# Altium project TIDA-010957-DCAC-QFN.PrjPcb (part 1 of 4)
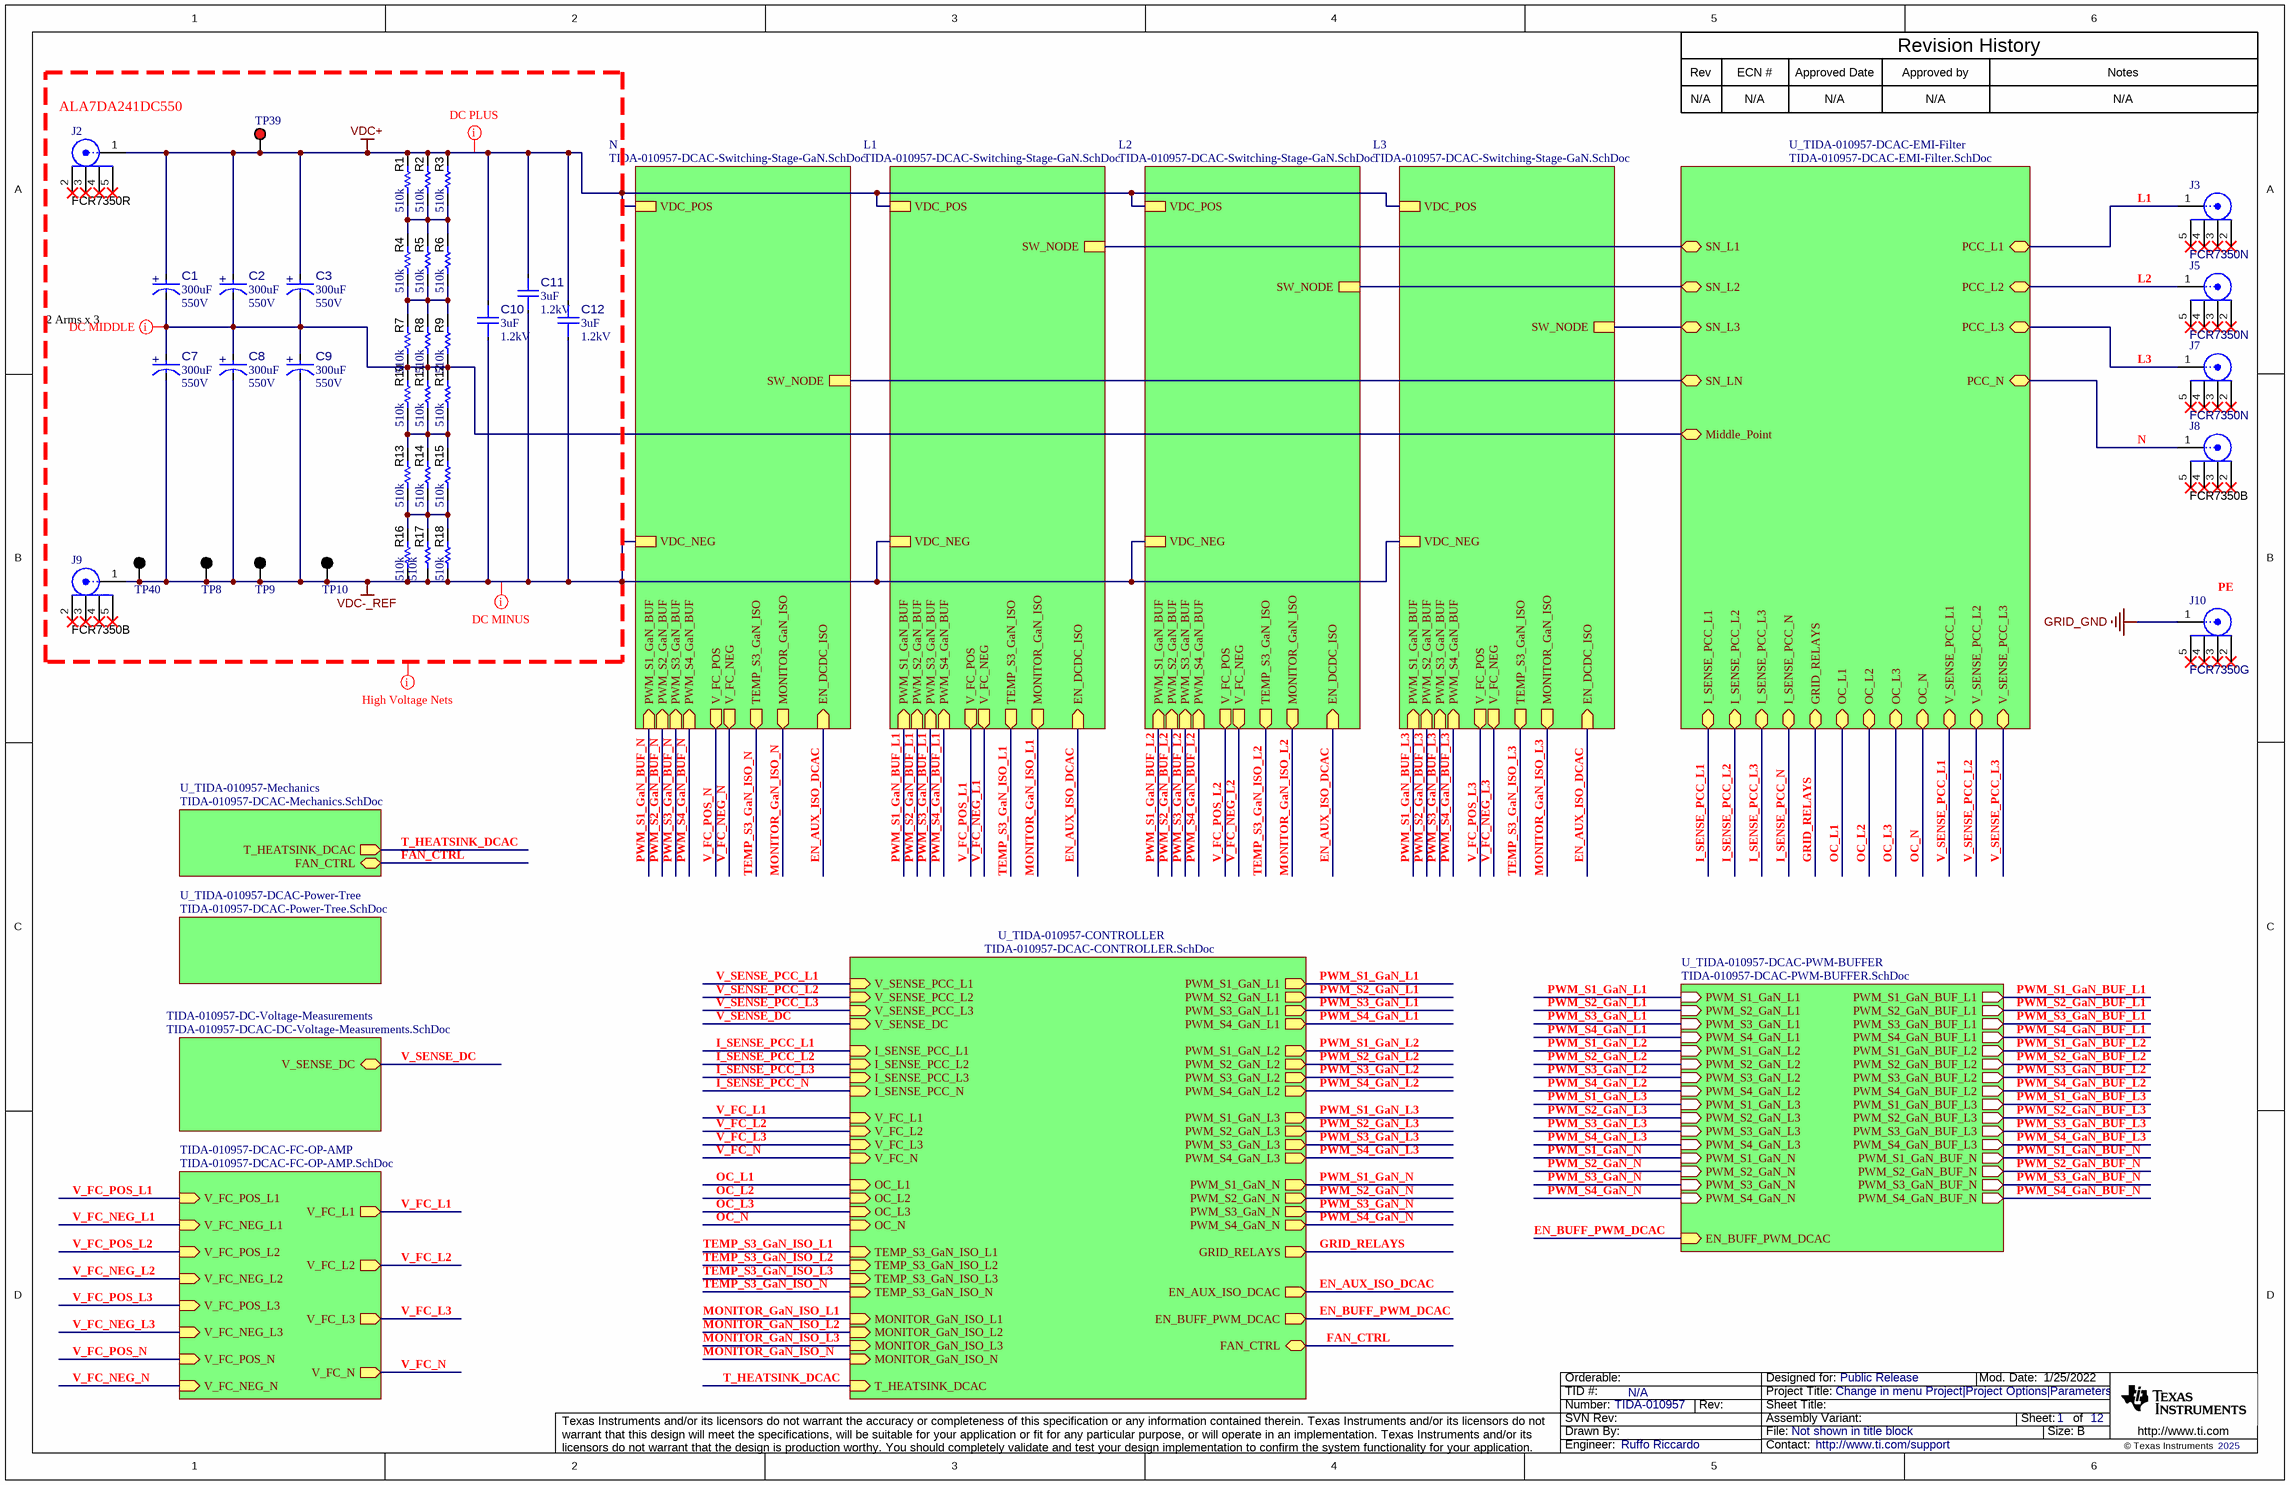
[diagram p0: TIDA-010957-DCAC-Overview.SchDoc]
CopyrightYear: 2025; PCB_Layout: Ruffo Riccardo; PCB_Rev: E1; PRJ_Customer: Public Release; PRJ_Engineer: Ruffo Riccardo; PRJ_Number: TIDA-010957; PRJ_Title: Change in menu Project|Project Options|Parameters; TechSupport: http://www.ti.com/support; TID: N/A
12 sheets, 1287 parts. Net scope: hierarchical (ports join the sheet entries above them; power ports are global).
Board file: TIDA-010957-DCAC-QFN-E1.PcbDoc
Sheets:
  TIDA-010957-DCAC-Overview.SchDoc
    U_TIDA-010957-CONTROLLER = TIDA-010957-DCAC-CONTROLLER.SchDoc
      U_TIDA-010957-DCAC-CAN = TIDA-010957-DCAC-CAN.SchDoc
    N = TIDA-010957-DCAC-Switching-Stage-GaN.SchDoc
    U_TIDA-010957-DCAC-EMI-Filter = TIDA-010957-DCAC-EMI-Filter.SchDoc
      TIDA-010957-DCAC-Current-Sensing = TIDA-010957-DCAC-Current-Sensing.SchDoc
      TIDA-010957-DCAC-Measurements-Voltages-AC = TIDA-010957-DCAC-Measurements-Voltages-AC.SchDoc
    TIDA-010957-DC-Voltage-Measurements = TIDA-010957-DCAC-DC-Voltage-Measurements.SchDoc
    TIDA-010957-DCAC-FC-OP-AMP = TIDA-010957-DCAC-FC-OP-AMP.SchDoc
    U_TIDA-010957-DCAC-PWM-BUFFER = TIDA-010957-DCAC-PWM-BUFFER.SchDoc
    U_TIDA-010957-DCAC-Power-Tree = TIDA-010957-DCAC-Power-Tree.SchDoc
    U_TIDA-010957-Mechanics = TIDA-010957-DCAC-Mechanics.SchDoc
    L1 = TIDA-010957-DCAC-Switching-Stage-GaN.SchDoc
    L2 = TIDA-010957-DCAC-Switching-Stage-GaN.SchDoc
    L3 = TIDA-010957-DCAC-Switching-Stage-GaN.SchDoc

## Sheet TIDA-010957-DCAC-Overview.SchDoc
size 431 x 279 mm; Date: Not shown in title block; ApprovedBy: Not shown in title block; CheckedBy: Not shown in title block; Author: Not shown in title block; CompanyName: Not shown in title block; Engineer: Not shown in title block; Organization: Not shown in title block; Address1: Not shown in title block; Address2: Not shown in title block; Address3: Not shown in title block; Address4: Not shown in title block; DocumentNumber: 1; Revision: Use project parameter SCH_Rev; SheetNumber: 1; SheetTotal: 12; PageSetup: Record=PageOptions¦CenterHorizontal=True¦CenterVertical=True¦PrintScale=1.00¦XCorrection=1.00¦YCorrection=1.00¦PrintKind=0¦BorderSize=5000000¦LeftOffset=0¦BottomOffset=0¦Orientation=2¦PaperLength=1000¦PaperWidth=1000¦Scale=100¦PaperSource=15¦PrintQuality=600¦MediaType=1¦DitherType=10¦PaperKind=Letter¦PrintScaleMode=1

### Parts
C1  ValueDisplayed: 300uF  VDC_V: 550V  [FP-ALA7DA301CF550_RADIAL-MFG]  (hidden comment: ALA7DA301CF550)
C2  ValueDisplayed: 300uF  VDC_V: 550V  [FP-ALA7DA301CF550_RADIAL-MFG]  (hidden comment: ALA7DA301CF550)
C3  ValueDisplayed: 300uF  VDC_V: 550V  [FP-ALA7DA301CF550_RADIAL-MFG]  (hidden comment: ALA7DA301CF550)
C7  ValueDisplayed: 300uF  VDC_V: 550V  [FP-ALA7DA301CF550_RADIAL-MFG]  (hidden comment: ALA7DA301CF550)
C8  ValueDisplayed: 300uF  VDC_V: 550V  [FP-ALA7DA301CF550_RADIAL-MFG]  (hidden comment: ALA7DA301CF550)
C9  ValueDisplayed: 300uF  VDC_V: 550V  [FP-ALA7DA301CF550_RADIAL-MFG]  (hidden comment: ALA7DA301CF550)
C10  ValueDisplayed: 3uF  VDC_V: 1.2kV  [FP-B32774X1305K000_RADIAL-MFG]  (hidden comment: B32774X1305K000)
C11  ValueDisplayed: 3uF  VDC_V: 1.2kV  [FP-B32774X1305K000_RADIAL-MFG]  (hidden comment: B32774X1305K000)
C12  ValueDisplayed: 3uF  VDC_V: 1.2kV  [FP-B32774X1305K000_RADIAL-MFG]  (hidden comment: B32774X1305K000)
J2  FCR7350R  [Cliff_FCR7350R]
J3  FCR7350N  [FP-FCR7350N_CONN_BANANA_JACK-MFG]
J5  FCR7350N  [FP-FCR7350N_CONN_BANANA_JACK-MFG]
J7  FCR7350N  [FP-FCR7350N_CONN_BANANA_JACK-MFG]
J8  FCR7350B  [Cliff_FCR7350B]
J9  FCR7350B  [Cliff_FCR7350B]
J10  FCR7350G  [FP-FCR7350G_CONN_BANANA_JACK-MFG]
R1  ValueDisplayed: 510k  [1206]  (hidden comment: CRCW1206510KJNEA)
R2  ValueDisplayed: 510k  [1206]  (hidden comment: CRCW1206510KJNEA)
R3  ValueDisplayed: 510k  [1206]  (hidden comment: CRCW1206510KJNEA)
R4  ValueDisplayed: 510k  [1206]  (hidden comment: CRCW1206510KJNEA)
R5  ValueDisplayed: 510k  [1206]  (hidden comment: CRCW1206510KJNEA)
R6  ValueDisplayed: 510k  [1206]  (hidden comment: CRCW1206510KJNEA)
R7  ValueDisplayed: 510k  [1206]  (hidden comment: CRCW1206510KJNEA)
R8  ValueDisplayed: 510k  [1206]  (hidden comment: CRCW1206510KJNEA)
R9  ValueDisplayed: 510k  [1206]  (hidden comment: CRCW1206510KJNEA)
R10  ValueDisplayed: 510k  [1206]  (hidden comment: CRCW1206510KJNEA)
R11  ValueDisplayed: 510k  [1206]  (hidden comment: CRCW1206510KJNEA)
R12  ValueDisplayed: 510k  [1206]  (hidden comment: CRCW1206510KJNEA)
R13  ValueDisplayed: 510k  [1206]  (hidden comment: CRCW1206510KJNEA)
R14  ValueDisplayed: 510k  [1206]  (hidden comment: CRCW1206510KJNEA)
R15  ValueDisplayed: 510k  [1206]  (hidden comment: CRCW1206510KJNEA)
R16  ValueDisplayed: 510k  [1206]  (hidden comment: CRCW1206510KJNEA)
R17  ValueDisplayed: 510k  [1206]  (hidden comment: CRCW1206510KJNEA)
R18  ValueDisplayed: 510k  [1206]  (hidden comment: CRCW1206510KJNEA)
TP8  5011  [Keystone5011]  (value not drawn)
TP9  5011  [Keystone5011]  (value not drawn)
TP10  5011  [Keystone5011]  (value not drawn)
TP39  5010  [Keystone5010]  (value not drawn)
TP40  5011  [Keystone5011]  (value not drawn)

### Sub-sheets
L1 = TIDA-010957-DCAC-Switching-Stage-GaN.SchDoc: PWM_S2_GaN_BUF (in), EN_DCDC_ISO (in), PWM_S1_GaN_BUF (in), PWM_S3_GaN_BUF (in), VDC_POS, SW_NODE, PWM_S4_GaN_BUF (in), VDC_NEG, V_FC_POS (out), V_FC_NEG (out), TEMP_S3_GaN_ISO (out), MONITOR_GaN_ISO (out)
L2 = TIDA-010957-DCAC-Switching-Stage-GaN.SchDoc: PWM_S2_GaN_BUF (in), EN_DCDC_ISO (in), PWM_S1_GaN_BUF (in), PWM_S3_GaN_BUF (in), VDC_POS, SW_NODE, PWM_S4_GaN_BUF (in), VDC_NEG, V_FC_POS (out), V_FC_NEG (out), TEMP_S3_GaN_ISO (out), MONITOR_GaN_ISO (out)
L3 = TIDA-010957-DCAC-Switching-Stage-GaN.SchDoc: PWM_S2_GaN_BUF (in), EN_DCDC_ISO (in), PWM_S1_GaN_BUF (in), PWM_S3_GaN_BUF (in), VDC_POS, SW_NODE, PWM_S4_GaN_BUF (in), VDC_NEG, V_FC_POS (out), V_FC_NEG (out), TEMP_S3_GaN_ISO (out), MONITOR_GaN_ISO (out)
N = TIDA-010957-DCAC-Switching-Stage-GaN.SchDoc: PWM_S2_GaN_BUF (in), EN_DCDC_ISO (in), PWM_S1_GaN_BUF (in), PWM_S3_GaN_BUF (in), VDC_POS, SW_NODE, PWM_S4_GaN_BUF (in), VDC_NEG, V_FC_POS (out), V_FC_NEG (out), TEMP_S3_GaN_ISO (out), MONITOR_GaN_ISO (out)
TIDA-010957-DC-Voltage-Measurements = TIDA-010957-DCAC-DC-Voltage-Measurements.SchDoc: V_SENSE_DC (bidir)
TIDA-010957-DCAC-FC-OP-AMP = TIDA-010957-DCAC-FC-OP-AMP.SchDoc: V_FC_POS_L1 (in), V_FC_L1 (out), V_FC_POS_L2 (in), V_FC_POS_L3 (in), V_FC_POS_N (in), V_FC_NEG_L1 (in), V_FC_NEG_L2 (in), V_FC_NEG_L3 (in), V_FC_NEG_N (in), V_FC_L2 (out), V_FC_L3 (out), V_FC_N (out)
U_TIDA-010957-CONTROLLER = TIDA-010957-DCAC-CONTROLLER.SchDoc: PWM_S1_GaN_L1 (out), PWM_S2_GaN_L1 (out), PWM_S3_GaN_L1 (out), PWM_S4_GaN_L1 (out), PWM_S1_GaN_L2 (out), PWM_S2_GaN_L2 (out), PWM_S3_GaN_L2 (out), PWM_S4_GaN_L2 (out), PWM_S1_GaN_L3 (out), PWM_S2_GaN_L3 (out), PWM_S3_GaN_L3 (out), PWM_S4_GaN_L3 (out), PWM_S1_GaN_N (out), PWM_S2_GaN_N (out), PWM_S3_GaN_N (out), PWM_S4_GaN_N (out), V_SENSE_DC (in), I_SENSE_PCC_L1 (in), I_SENSE_PCC_L2 (in), I_SENSE_PCC_L3 (in), OC_L1 (in), OC_L2 (in), OC_L3 (in), V_SENSE_PCC_L1 (in), V_SENSE_PCC_L2 (in), V_SENSE_PCC_L3 (in), V_FC_L1 (in), V_FC_L2 (in), V_FC_L3 (in), V_FC_N (in), GRID_RELAYS (out), EN_BUFF_PWM_DCAC (out), EN_AUX_ISO_DCAC (out), TEMP_S3_GaN_ISO_L1 (in), MONITOR_GaN_ISO_L1 (in), TEMP_S3_GaN_ISO_L2 (in), TEMP_S3_GaN_ISO_L3 (in), TEMP_S3_GaN_ISO_N (in), MONITOR_GaN_ISO_L2 (in), MONITOR_GaN_ISO_L3 (in), MONITOR_GaN_ISO_N (in), OC_N (in), I_SENSE_PCC_N (in), FAN_CTRL (bidir), T_HEATSINK_DCAC (in)
U_TIDA-010957-DCAC-EMI-Filter = TIDA-010957-DCAC-EMI-Filter.SchDoc: SN_L1 (bidir), SN_L2 (bidir), SN_L3 (bidir), SN_LN (bidir), PCC_L1 (bidir), PCC_L2 (bidir), PCC_L3 (bidir), PCC_N (bidir), OC_L1 (bidir), OC_L2 (bidir), OC_L3 (bidir), V_SENSE_PCC_L1 (bidir), V_SENSE_PCC_L2 (bidir), V_SENSE_PCC_L3 (bidir), I_SENSE_PCC_L1 (bidir), I_SENSE_PCC_L2 (bidir), I_SENSE_PCC_L3 (bidir), GRID_RELAYS (bidir), Middle_Point (bidir), I_SENSE_PCC_N (bidir), OC_N (bidir)
U_TIDA-010957-DCAC-Power-Tree = TIDA-010957-DCAC-Power-Tree.SchDoc: no entries
U_TIDA-010957-DCAC-PWM-BUFFER = TIDA-010957-DCAC-PWM-BUFFER.SchDoc: PWM_S1_GaN_BUF_L1 (out), PWM_S2_GaN_BUF_L1 (out), PWM_S3_GaN_BUF_L1 (out), PWM_S4_GaN_BUF_L1 (out), PWM_S1_GaN_BUF_L2 (out), PWM_S2_GaN_BUF_L2 (out), PWM_S3_GaN_BUF_L2 (out), PWM_S4_GaN_BUF_L2 (out), PWM_S1_GaN_BUF_L3 (out), PWM_S2_GaN_BUF_L3 (out), PWM_S3_GaN_BUF_L3 (out), PWM_S4_GaN_BUF_L3 (out), PWM_S1_GaN_BUF_N (out), PWM_S2_GaN_BUF_N (out), PWM_S3_GaN_BUF_N (out), PWM_S4_GaN_BUF_N (out), PWM_S1_GaN_L1 (in), PWM_S2_GaN_L1 (in), PWM_S3_GaN_L1 (in), PWM_S4_GaN_L1 (in), PWM_S1_GaN_L2 (in), PWM_S2_GaN_L2 (in), PWM_S3_GaN_L2 (in), PWM_S4_GaN_L2 (in), PWM_S1_GaN_L3 (in), PWM_S2_GaN_L3 (in), PWM_S3_GaN_L3 (in), PWM_S4_GaN_L3 (in), PWM_S1_GaN_N (in), PWM_S2_GaN_N (in), PWM_S3_GaN_N (in), PWM_S4_GaN_N (in), EN_BUFF_PWM_DCAC (in)
U_TIDA-010957-Mechanics = TIDA-010957-DCAC-Mechanics.SchDoc: T_HEATSINK_DCAC (out), FAN_CTRL (bidir)

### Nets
GRID_GND: J10.1
VDC+: C1.2(ANODE) C2.2(ANODE) C3.2(ANODE) C10.2 C11.2 C12.2 J2.1 R1.2 R2.2 R3.2 TP39.1 ; sheet N/VDC_POS, sheet L1/VDC_POS, sheet L2/VDC_POS, sheet L3/VDC_POS
VDC-_REF: C7.1(CATHODE) C8.1(CATHODE) C9.1(CATHODE) C10.1 C11.1 C12.1 J9.1 R16.1 R17.1 R18.1 TP8.1 TP9.1 TP10.1 TP40.1 ; sheet N/VDC_NEG, sheet L1/VDC_NEG, sheet L2/VDC_NEG, sheet L3/VDC_NEG  [project net GND_S4_GaN]
EN_AUX_ISO_DCAC: sheet U_TIDA-010957-CONTROLLER/EN_AUX_ISO_DCAC, sheet N/EN_DCDC_ISO, sheet L1/EN_DCDC_ISO, sheet L2/EN_DCDC_ISO, sheet L3/EN_DCDC_ISO
EN_BUFF_PWM_DCAC: sheet U_TIDA-010957-CONTROLLER/EN_BUFF_PWM_DCAC, sheet U_TIDA-010957-DCAC-PWM-BUFFER/EN_BUFF_PWM_DCAC  [project net BUFF_EN]
FAN_CTRL: sheet U_TIDA-010957-CONTROLLER/FAN_CTRL, sheet U_TIDA-010957-Mechanics/FAN_CTRL
GND_S2_GaN: sheet N/SW_NODE, sheet U_TIDA-010957-DCAC-EMI-Filter/SN_LN
GND_S2_GaN: sheet U_TIDA-010957-DCAC-EMI-Filter/SN_L1, sheet L1/SW_NODE  [a separate net that carries the same name]
GND_S2_GaN: sheet U_TIDA-010957-DCAC-EMI-Filter/SN_L2, sheet L2/SW_NODE  [a separate net that carries the same name]
GND_S2_GaN: sheet U_TIDA-010957-DCAC-EMI-Filter/SN_L3, sheet L3/SW_NODE  [a separate net that carries the same name]
GRID_RELAYS: sheet U_TIDA-010957-CONTROLLER/GRID_RELAYS, sheet U_TIDA-010957-DCAC-EMI-Filter/GRID_RELAYS
I_SENSE_PCC_L1: sheet U_TIDA-010957-CONTROLLER/I_SENSE_PCC_L1, sheet U_TIDA-010957-DCAC-EMI-Filter/I_SENSE_PCC_L1
I_SENSE_PCC_L2: sheet U_TIDA-010957-CONTROLLER/I_SENSE_PCC_L2, sheet U_TIDA-010957-DCAC-EMI-Filter/I_SENSE_PCC_L2
I_SENSE_PCC_L3: sheet U_TIDA-010957-CONTROLLER/I_SENSE_PCC_L3, sheet U_TIDA-010957-DCAC-EMI-Filter/I_SENSE_PCC_L3
I_SENSE_PCC_N: sheet U_TIDA-010957-CONTROLLER/I_SENSE_PCC_N, sheet U_TIDA-010957-DCAC-EMI-Filter/I_SENSE_PCC_N
Middle_Point: C1.1(CATHODE) C2.1(CATHODE) C3.1(CATHODE) C7.2(ANODE) C8.2(ANODE) C9.2(ANODE) R7.1 R8.1 R9.1 R10.2 R11.2 R12.2 ; sheet U_TIDA-010957-DCAC-EMI-Filter/Middle_Point
MONITOR_GaN_ISO_L1: sheet U_TIDA-010957-CONTROLLER/MONITOR_GaN_ISO_L1, sheet L1/MONITOR_GaN_ISO
MONITOR_GaN_ISO_L2: sheet U_TIDA-010957-CONTROLLER/MONITOR_GaN_ISO_L2, sheet L2/MONITOR_GaN_ISO
MONITOR_GaN_ISO_L3: sheet U_TIDA-010957-CONTROLLER/MONITOR_GaN_ISO_L3, sheet L3/MONITOR_GaN_ISO
MONITOR_GaN_ISO_N: sheet U_TIDA-010957-CONTROLLER/MONITOR_GaN_ISO_N, sheet N/MONITOR_GaN_ISO
OC_L1: sheet U_TIDA-010957-CONTROLLER/OC_L1, sheet U_TIDA-010957-DCAC-EMI-Filter/OC_L1
OC_L2: sheet U_TIDA-010957-CONTROLLER/OC_L2, sheet U_TIDA-010957-DCAC-EMI-Filter/OC_L2
OC_L3: sheet U_TIDA-010957-CONTROLLER/OC_L3, sheet U_TIDA-010957-DCAC-EMI-Filter/OC_L3
OC_N: sheet U_TIDA-010957-CONTROLLER/OC_N, sheet U_TIDA-010957-DCAC-EMI-Filter/OC_N
PCC_L1: J3.1 ; sheet U_TIDA-010957-DCAC-EMI-Filter/PCC_L1
PCC_L2: J5.1 ; sheet U_TIDA-010957-DCAC-EMI-Filter/PCC_L2
PCC_L3: J7.1 ; sheet U_TIDA-010957-DCAC-EMI-Filter/PCC_L3
PCC_N: J8.1 ; sheet U_TIDA-010957-DCAC-EMI-Filter/PCC_N
PWM_S1_GaN_BUF_L1: sheet U_TIDA-010957-DCAC-PWM-BUFFER/PWM_S1_GaN_BUF_L1, sheet L1/PWM_S1_GaN_BUF
PWM_S1_GaN_BUF_L2: sheet U_TIDA-010957-DCAC-PWM-BUFFER/PWM_S1_GaN_BUF_L2, sheet L2/PWM_S1_GaN_BUF
PWM_S1_GaN_BUF_L3: sheet U_TIDA-010957-DCAC-PWM-BUFFER/PWM_S1_GaN_BUF_L3, sheet L3/PWM_S1_GaN_BUF
PWM_S1_GaN_BUF_N: sheet N/PWM_S1_GaN_BUF, sheet U_TIDA-010957-DCAC-PWM-BUFFER/PWM_S1_GaN_BUF_N
PWM_S1_GaN_L1: sheet U_TIDA-010957-CONTROLLER/PWM_S1_GaN_L1, sheet U_TIDA-010957-DCAC-PWM-BUFFER/PWM_S1_GaN_L1
PWM_S1_GaN_L2: sheet U_TIDA-010957-CONTROLLER/PWM_S1_GaN_L2, sheet U_TIDA-010957-DCAC-PWM-BUFFER/PWM_S1_GaN_L2
PWM_S1_GaN_L3: sheet U_TIDA-010957-CONTROLLER/PWM_S1_GaN_L3, sheet U_TIDA-010957-DCAC-PWM-BUFFER/PWM_S1_GaN_L3
PWM_S1_GaN_N: sheet U_TIDA-010957-CONTROLLER/PWM_S1_GaN_N, sheet U_TIDA-010957-DCAC-PWM-BUFFER/PWM_S1_GaN_N
PWM_S2_GaN_BUF_L1: sheet U_TIDA-010957-DCAC-PWM-BUFFER/PWM_S2_GaN_BUF_L1, sheet L1/PWM_S2_GaN_BUF
PWM_S2_GaN_BUF_L2: sheet U_TIDA-010957-DCAC-PWM-BUFFER/PWM_S2_GaN_BUF_L2, sheet L2/PWM_S2_GaN_BUF
PWM_S2_GaN_BUF_L3: sheet U_TIDA-010957-DCAC-PWM-BUFFER/PWM_S2_GaN_BUF_L3, sheet L3/PWM_S2_GaN_BUF
PWM_S2_GaN_BUF_N: sheet N/PWM_S2_GaN_BUF, sheet U_TIDA-010957-DCAC-PWM-BUFFER/PWM_S2_GaN_BUF_N
PWM_S2_GaN_L1: sheet U_TIDA-010957-CONTROLLER/PWM_S2_GaN_L1, sheet U_TIDA-010957-DCAC-PWM-BUFFER/PWM_S2_GaN_L1
PWM_S2_GaN_L2: sheet U_TIDA-010957-CONTROLLER/PWM_S2_GaN_L2, sheet U_TIDA-010957-DCAC-PWM-BUFFER/PWM_S2_GaN_L2
PWM_S2_GaN_L3: sheet U_TIDA-010957-CONTROLLER/PWM_S2_GaN_L3, sheet U_TIDA-010957-DCAC-PWM-BUFFER/PWM_S2_GaN_L3
PWM_S2_GaN_N: sheet U_TIDA-010957-CONTROLLER/PWM_S2_GaN_N, sheet U_TIDA-010957-DCAC-PWM-BUFFER/PWM_S2_GaN_N
PWM_S3_GaN_BUF_L1: sheet U_TIDA-010957-DCAC-PWM-BUFFER/PWM_S3_GaN_BUF_L1, sheet L1/PWM_S3_GaN_BUF
PWM_S3_GaN_BUF_L2: sheet U_TIDA-010957-DCAC-PWM-BUFFER/PWM_S3_GaN_BUF_L2, sheet L2/PWM_S3_GaN_BUF
PWM_S3_GaN_BUF_L3: sheet U_TIDA-010957-DCAC-PWM-BUFFER/PWM_S3_GaN_BUF_L3, sheet L3/PWM_S3_GaN_BUF
PWM_S3_GaN_BUF_N: sheet N/PWM_S3_GaN_BUF, sheet U_TIDA-010957-DCAC-PWM-BUFFER/PWM_S3_GaN_BUF_N
PWM_S3_GaN_L1: sheet U_TIDA-010957-CONTROLLER/PWM_S3_GaN_L1, sheet U_TIDA-010957-DCAC-PWM-BUFFER/PWM_S3_GaN_L1
PWM_S3_GaN_L2: sheet U_TIDA-010957-CONTROLLER/PWM_S3_GaN_L2, sheet U_TIDA-010957-DCAC-PWM-BUFFER/PWM_S3_GaN_L2
PWM_S3_GaN_L3: sheet U_TIDA-010957-CONTROLLER/PWM_S3_GaN_L3, sheet U_TIDA-010957-DCAC-PWM-BUFFER/PWM_S3_GaN_L3
PWM_S3_GaN_N: sheet U_TIDA-010957-CONTROLLER/PWM_S3_GaN_N, sheet U_TIDA-010957-DCAC-PWM-BUFFER/PWM_S3_GaN_N
PWM_S4_GaN_BUF_L1: sheet U_TIDA-010957-DCAC-PWM-BUFFER/PWM_S4_GaN_BUF_L1, sheet L1/PWM_S4_GaN_BUF
PWM_S4_GaN_BUF_L2: sheet U_TIDA-010957-DCAC-PWM-BUFFER/PWM_S4_GaN_BUF_L2, sheet L2/PWM_S4_GaN_BUF
PWM_S4_GaN_BUF_L3: sheet U_TIDA-010957-DCAC-PWM-BUFFER/PWM_S4_GaN_BUF_L3, sheet L3/PWM_S4_GaN_BUF
PWM_S4_GaN_BUF_N: sheet N/PWM_S4_GaN_BUF, sheet U_TIDA-010957-DCAC-PWM-BUFFER/PWM_S4_GaN_BUF_N
PWM_S4_GaN_L1: sheet U_TIDA-010957-CONTROLLER/PWM_S4_GaN_L1, sheet U_TIDA-010957-DCAC-PWM-BUFFER/PWM_S4_GaN_L1
PWM_S4_GaN_L2: sheet U_TIDA-010957-CONTROLLER/PWM_S4_GaN_L2, sheet U_TIDA-010957-DCAC-PWM-BUFFER/PWM_S4_GaN_L2
PWM_S4_GaN_L3: sheet U_TIDA-010957-CONTROLLER/PWM_S4_GaN_L3, sheet U_TIDA-010957-DCAC-PWM-BUFFER/PWM_S4_GaN_L3
PWM_S4_GaN_N: sheet U_TIDA-010957-CONTROLLER/PWM_S4_GaN_N, sheet U_TIDA-010957-DCAC-PWM-BUFFER/PWM_S4_GaN_N
T_HEATSINK_DCAC: sheet U_TIDA-010957-CONTROLLER/T_HEATSINK_DCAC, sheet U_TIDA-010957-Mechanics/T_HEATSINK_DCAC
TEMP_S3_GaN_ISO_L1: sheet U_TIDA-010957-CONTROLLER/TEMP_S3_GaN_ISO_L1, sheet L1/TEMP_S3_GaN_ISO
TEMP_S3_GaN_ISO_L2: sheet U_TIDA-010957-CONTROLLER/TEMP_S3_GaN_ISO_L2, sheet L2/TEMP_S3_GaN_ISO
TEMP_S3_GaN_ISO_L3: sheet U_TIDA-010957-CONTROLLER/TEMP_S3_GaN_ISO_L3, sheet L3/TEMP_S3_GaN_ISO
TEMP_S3_GaN_ISO_N: sheet U_TIDA-010957-CONTROLLER/TEMP_S3_GaN_ISO_N, sheet N/TEMP_S3_GaN_ISO
V_FC_L1: sheet U_TIDA-010957-CONTROLLER/V_FC_L1, sheet TIDA-010957-DCAC-FC-OP-AMP/V_FC_L1
V_FC_L2: sheet U_TIDA-010957-CONTROLLER/V_FC_L2, sheet TIDA-010957-DCAC-FC-OP-AMP/V_FC_L2
V_FC_L3: sheet U_TIDA-010957-CONTROLLER/V_FC_L3, sheet TIDA-010957-DCAC-FC-OP-AMP/V_FC_L3
V_FC_N: sheet U_TIDA-010957-CONTROLLER/V_FC_N, sheet TIDA-010957-DCAC-FC-OP-AMP/V_FC_N
V_FC_NEG_L1: sheet TIDA-010957-DCAC-FC-OP-AMP/V_FC_NEG_L1, sheet L1/V_FC_NEG
V_FC_NEG_L2: sheet TIDA-010957-DCAC-FC-OP-AMP/V_FC_NEG_L2, sheet L2/V_FC_NEG
V_FC_NEG_L3: sheet TIDA-010957-DCAC-FC-OP-AMP/V_FC_NEG_L3, sheet L3/V_FC_NEG
V_FC_NEG_N: sheet N/V_FC_NEG, sheet TIDA-010957-DCAC-FC-OP-AMP/V_FC_NEG_N
V_FC_POS_L1: sheet TIDA-010957-DCAC-FC-OP-AMP/V_FC_POS_L1, sheet L1/V_FC_POS
V_FC_POS_L2: sheet TIDA-010957-DCAC-FC-OP-AMP/V_FC_POS_L2, sheet L2/V_FC_POS
V_FC_POS_L3: sheet TIDA-010957-DCAC-FC-OP-AMP/V_FC_POS_L3, sheet L3/V_FC_POS
V_FC_POS_N: sheet N/V_FC_POS, sheet TIDA-010957-DCAC-FC-OP-AMP/V_FC_POS_N
V_SENSE_DC: sheet U_TIDA-010957-CONTROLLER/V_SENSE_DC, sheet TIDA-010957-DC-Voltage-Measurements/V_SENSE_DC
V_SENSE_PCC_L1: sheet U_TIDA-010957-CONTROLLER/V_SENSE_PCC_L1, sheet U_TIDA-010957-DCAC-EMI-Filter/V_SENSE_PCC_L1
V_SENSE_PCC_L2: sheet U_TIDA-010957-CONTROLLER/V_SENSE_PCC_L2, sheet U_TIDA-010957-DCAC-EMI-Filter/V_SENSE_PCC_L2
V_SENSE_PCC_L3: sheet U_TIDA-010957-CONTROLLER/V_SENSE_PCC_L3, sheet U_TIDA-010957-DCAC-EMI-Filter/V_SENSE_PCC_L3
NetR1_1: R1.1 R2.1 R3.1 R4.2 R5.2 R6.2
NetR4_1: R4.1 R5.1 R6.1 R7.2 R8.2 R9.2
NetR10_1: R10.1 R11.1 R12.1 R13.2 R14.2 R15.2
NetR13_1: R13.1 R14.1 R15.1 R16.2 R17.2 R18.2

Not connected (* = marked no-connect by the designer): J2 2* 3* 4* 5*; J3 2* 3* 4* 5*; J5 2* 3* 4* 5*; J7 2* 3* 4* 5*; J8 2* 3* 4* 5*; J9 2* 3* 4* 5*; J10 2* 3* 4* 5*

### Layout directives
net class HV_NET: VDC+, VDC-_REF
net class DC PLUS: VDC+
net class DC MINUS: GND_S4_GaN
net class DC MIDDLE: Middle_Point

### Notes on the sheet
- Rev
- N/A
- ECN #
- Approved Date
- Approved by
- Revision History
- Notes
- (near J2) ALA7DA241DC550
- (near J3) L1
- (near J5) L2
- 2 Arms x 3
- (near J7) L3
- N
- (near J10) PE

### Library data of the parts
C1-C3 C7-C9 = CMP-0124364-1: 300 µF 550 V Aluminum Electrolytic Capacitors Radial, Can - Snap-In 567mOhm @ 100Hz 13000 Hrs @ 85°C; Manufacturer: KEMET; AEC Grade: Grade 3; AEC Qualified: Yes; Cap_F: 300µF; IRMS_A: 4.3A; SizeZ_mm: 52mm; Tolerance_%: 20%; Esr: 0.567; Leakage Current: 990uA; Life: 13000Hours; Value: 300µF
C10-C12 = CMP-0124365-1: 3 µF Film Capacitor 1200V (1.2kV) Polypropylene (PP), Metallized Radial; Manufacturer: TDK; AEC Qualified: No; Cap_F: 3µF; SizeZ_mm: 27.5mm; Tolerance_%: 10%; Value: 3µF
J2 = CMP-0055799-1: Panel Socket, 24A, R/A, Gold, TH; Manufacturer: Cliff Electronic Components; CNHeader: FALSE; Gender: Female; Voltage_V: 1kV
J3 J5 J7 = CMP-0098296-2: Banana Test Connector, Socket, PCB Mount, 24 A, 1 kV, Gold Plated Contacts, Brown; Manufacturer: CLIFF Electronic Components; Current_A: 24A; Voltage_V: 1kV; AEC Qualified: No; Conn Orientation: Right Angle; Is Female: yes; SizeZ_mm: 11.6mm; Standoff Height: 0.7mm
J8 J9 = CMP-0055798-1: Panel Socket, 24A, R/A, Gold, TH; Manufacturer: Cliff Electronic Components; CNHeader: FALSE; Gender: Female; Voltage_V: 1kV
J10 = CMP-0098294-2: Banana Test Connector, Socket, PCB Mount, 24 A, 1 kV, Gold Plated Contacts, Green; Manufacturer: CLIFF Electronic Components; Current_A: 24A; Voltage_V: 1kV; AEC Qualified: No; Conn Orientation: Right Angle; SizeZ_mm: 11.6mm; Standoff Height: 0.7mm
R1-R18 = CMP-0018695-3: RES, 510 k, 5%, 0.25 W, AEC-Q200 Grade 0, 1206; Manufacturer: Vishay-Dale; Power_W: 250mW; TempCo: 200 ppm/C; Value: 510k; EIA_Code: E24; SizeX_mm: 3.2; SizeY_mm: 1.6; SizeZ_mm: 1.35; Value2: 0.25W; SizeArea_mm2: 5.12; AEC Qualified: Y; VDC_V: 200V; AEC Category: Q200; AEC Grade: 0
TP8-TP10 TP40 = CMP-0055148-2: Test Point, Multipurpose, Black, TH; Manufacturer: Keystone Electronics; CNHeader: FALSE; ContactFinish: Silver; Green_REACh: Passed; Green_Lifecycle: Active; CT: TRUE
TP39 = CMP-0055147-2: Test Point, Multipurpose, Red, TH; Manufacturer: Keystone Electronics; CT: TRUE; ContactFinish: Silver; Green_Lifecycle: Active; CNHeader: FALSE; Green_REACh: Passed

## Sheet TIDA-010957-DCAC-CONTROLLER.SchDoc
size 431 x 279 mm; Date: Not shown in title block; ApprovedBy: Not shown in title block; CheckedBy: Not shown in title block; Author: Not shown in title block; CompanyName: Not shown in title block; Engineer: Not shown in title block; Organization: Not shown in title block; Address1: Not shown in title block; Address2: Not shown in title block; Address3: Not shown in title block; Address4: Not shown in title block; DocumentNumber: 2; Revision: Use project parameter SCH_Rev; SheetNumber: 3; SheetTotal: 12; PageSetup: Record=PageOptions¦CenterHorizontal=True¦CenterVertical=True¦PrintScale=1.00¦XCorrection=1.00¦YCorrection=1.00¦PrintKind=0¦BorderSize=5000000¦LeftOffset=0¦BottomOffset=0¦Orientation=2¦PaperLength=1000¦PaperWidth=1000¦Scale=100¦PaperSource=15¦PrintQuality=600¦MediaType=1¦DitherType=10¦PaperKind=Letter¦PrintScaleMode=1
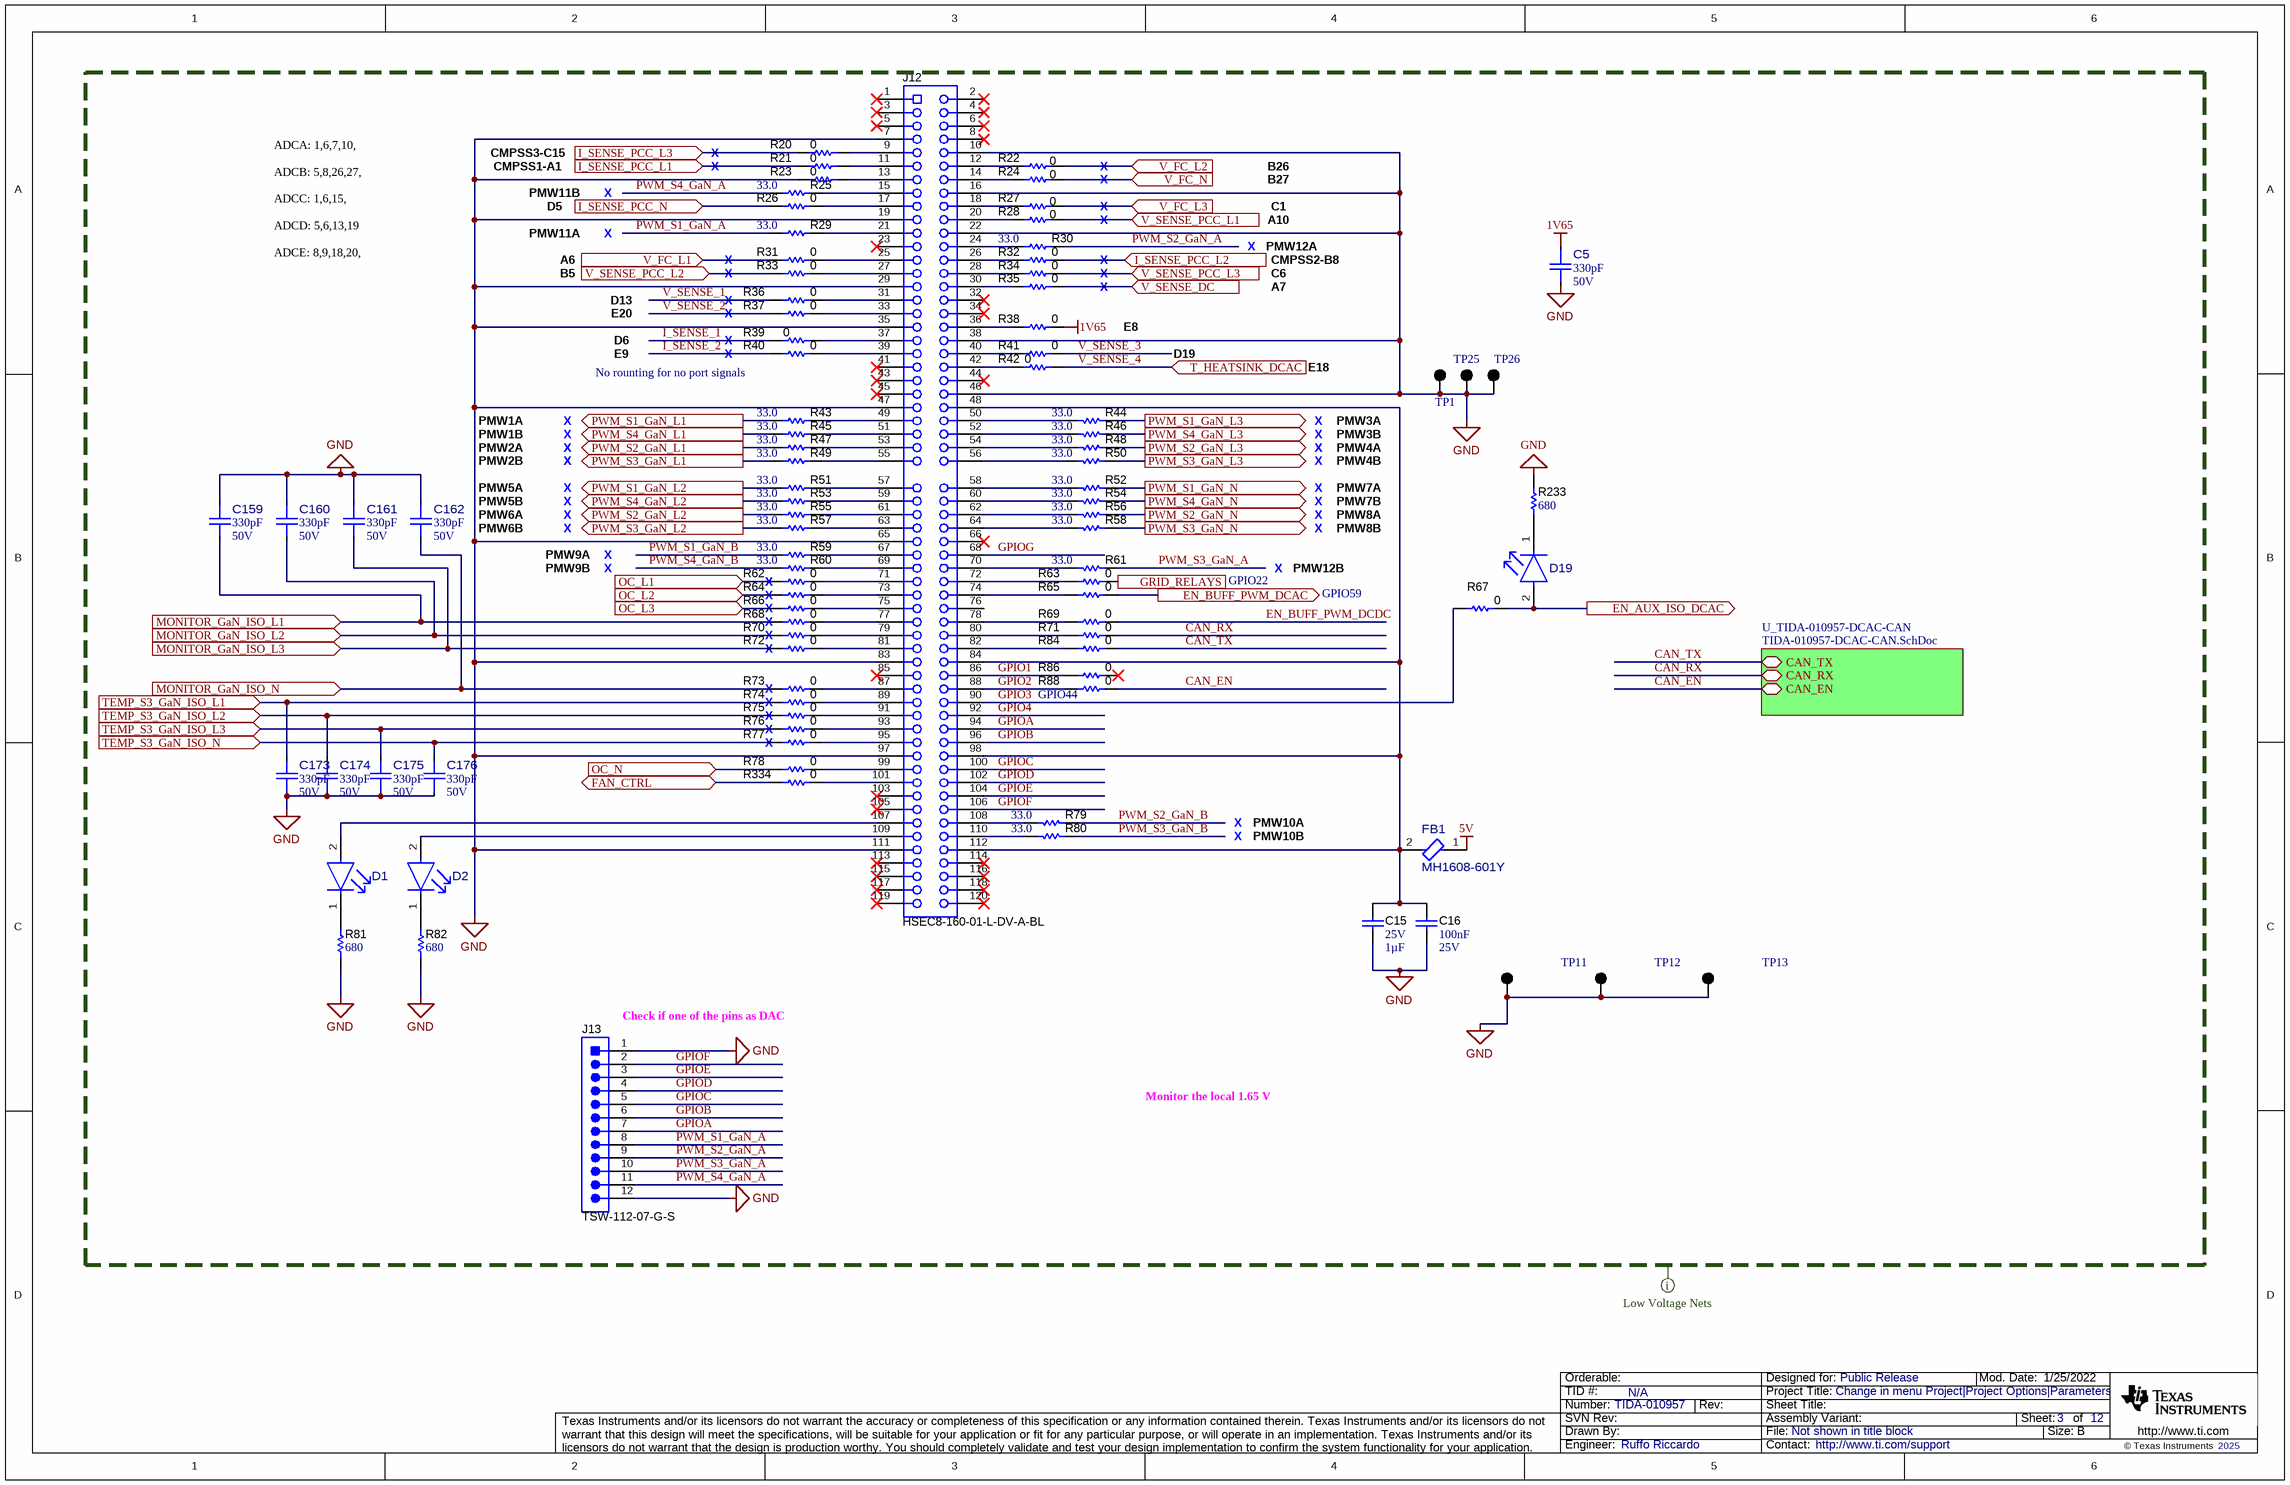
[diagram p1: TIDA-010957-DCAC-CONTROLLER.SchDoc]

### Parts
C5  ValueDisplayed: 330pF  VDC_V: 50V  [FP-CGA3E2C0G1H331J080AA_0603-MFG]  (hidden comment: CGA3E2C0G1H331J080AA)
C15  VDC_V: 25V  ValueDisplayed: 1µF  [0603]  (hidden comment: TMK107BJ105KA-T)
C16  Cap_F: 100nF  VDC_V: 25V  [0603]  (hidden comment: 06033C104JAT2A)
C159  ValueDisplayed: 330pF  VDC_V: 50V  [FP-CGA3E2C0G1H331J080AA_0603-MFG]  (hidden comment: CGA3E2C0G1H331J080AA)
C160  ValueDisplayed: 330pF  VDC_V: 50V  [FP-CGA3E2C0G1H331J080AA_0603-MFG]  (hidden comment: CGA3E2C0G1H331J080AA)
C161  ValueDisplayed: 330pF  VDC_V: 50V  [FP-CGA3E2C0G1H331J080AA_0603-MFG]  (hidden comment: CGA3E2C0G1H331J080AA)
C162  ValueDisplayed: 330pF  VDC_V: 50V  [FP-CGA3E2C0G1H331J080AA_0603-MFG]  (hidden comment: CGA3E2C0G1H331J080AA)
C173  ValueDisplayed: 330pF  VDC_V: 50V  [FP-CGA3E2C0G1H331J080AA_0603-MFG]  (hidden comment: CGA3E2C0G1H331J080AA)
C174  ValueDisplayed: 330pF  VDC_V: 50V  [FP-CGA3E2C0G1H331J080AA_0603-MFG]  (hidden comment: CGA3E2C0G1H331J080AA)
C175  ValueDisplayed: 330pF  VDC_V: 50V  [FP-CGA3E2C0G1H331J080AA_0603-MFG]  (hidden comment: CGA3E2C0G1H331J080AA)
C176  ValueDisplayed: 330pF  VDC_V: 50V  [FP-CGA3E2C0G1H331J080AA_0603-MFG]  (hidden comment: CGA3E2C0G1H331J080AA)
D1  KG DELLS1.22-JGKH-24  [FP-KG DELLS1.22-JGKH-24_0603-MFG]  (value not drawn)
D2  KG DELLS1.22-JGKH-24  [FP-KG DELLS1.22-JGKH-24_0603-MFG]  (value not drawn)
D19  KG DELLS1.22-JGKH-24  [FP-KG DELLS1.22-JGKH-24_0603-MFG]  (value not drawn)
FB1  MH1608-601Y  [FP-MH1608-601Y_0603-MFG]
J12  HSEC8-160-01-L-DV-A-BL  [controlCARD-120HSEC]
J13  TSW-112-07-G-S  [TSW-112-07-G-S]
R20  ValueDisplayed: 0  [0603]  (hidden comment: RCS06030000Z0EA)
R21  ValueDisplayed: 0  [0603]  (hidden comment: RCS06030000Z0EA)
R22  ValueDisplayed: 0  [0603]  (hidden comment: RCS06030000Z0EA)
R23  ValueDisplayed: 0  [0603]  (hidden comment: RCS06030000Z0EA)
R24  ValueDisplayed: 0  [0603]  (hidden comment: RCS06030000Z0EA)
R25  ValueDisplayed: 33.0  [0402L]  (hidden comment: ERJ-2RKF33R0X)
R26  ValueDisplayed: 0  [0603]  (hidden comment: RCS06030000Z0EA)
R27  ValueDisplayed: 0  [0603]  (hidden comment: RCS06030000Z0EA)
R28  ValueDisplayed: 0  [0603]  (hidden comment: RCS06030000Z0EA)
R29  ValueDisplayed: 33.0  [0402L]  (hidden comment: ERJ-2RKF33R0X)
R30  ValueDisplayed: 33.0  [0402L]  (hidden comment: ERJ-2RKF33R0X)
R31  ValueDisplayed: 0  [0603]  (hidden comment: RCS06030000Z0EA)
R32  ValueDisplayed: 0  [0603]  (hidden comment: RCS06030000Z0EA)
R33  ValueDisplayed: 0  [0603]  (hidden comment: RCS06030000Z0EA)
R34  ValueDisplayed: 0  [0603]  (hidden comment: RCS06030000Z0EA)
R35  ValueDisplayed: 0  [0603]  (hidden comment: RCS06030000Z0EA)
R36  ValueDisplayed: 0  [0603]  (hidden comment: RCS06030000Z0EA)
R37  ValueDisplayed: 0  [0603]  (hidden comment: RCS06030000Z0EA)
R38  ValueDisplayed: 0  [0603]  (hidden comment: RCS06030000Z0EA)
R39  ValueDisplayed: 0  [0603]  (hidden comment: RCS06030000Z0EA)
R40  ValueDisplayed: 0  [0603]  (hidden comment: RCS06030000Z0EA)
R41  ValueDisplayed: 0  [0603]  (hidden comment: RCS06030000Z0EA)
R42  ValueDisplayed: 0  [0603]  (hidden comment: RCS06030000Z0EA)
R43  ValueDisplayed: 33.0  [0402L]  (hidden comment: ERJ-2RKF33R0X)
R44  ValueDisplayed: 33.0  [0402L]  (hidden comment: ERJ-2RKF33R0X)
R45  ValueDisplayed: 33.0  [0402L]  (hidden comment: ERJ-2RKF33R0X)
R46  ValueDisplayed: 33.0  [0402L]  (hidden comment: ERJ-2RKF33R0X)
R47  ValueDisplayed: 33.0  [0402L]  (hidden comment: ERJ-2RKF33R0X)
R48  ValueDisplayed: 33.0  [0402L]  (hidden comment: ERJ-2RKF33R0X)
R49  ValueDisplayed: 33.0  [0402L]  (hidden comment: ERJ-2RKF33R0X)
R50  ValueDisplayed: 33.0  [0402L]  (hidden comment: ERJ-2RKF33R0X)
R51  ValueDisplayed: 33.0  [0402L]  (hidden comment: ERJ-2RKF33R0X)
R52  ValueDisplayed: 33.0  [0402L]  (hidden comment: ERJ-2RKF33R0X)
R53  ValueDisplayed: 33.0  [0402L]  (hidden comment: ERJ-2RKF33R0X)
R54  ValueDisplayed: 33.0  [0402L]  (hidden comment: ERJ-2RKF33R0X)
R55  ValueDisplayed: 33.0  [0402L]  (hidden comment: ERJ-2RKF33R0X)
R56  ValueDisplayed: 33.0  [0402L]  (hidden comment: ERJ-2RKF33R0X)
R57  ValueDisplayed: 33.0  [0402L]  (hidden comment: ERJ-2RKF33R0X)
R58  ValueDisplayed: 33.0  [0402L]  (hidden comment: ERJ-2RKF33R0X)
R59  ValueDisplayed: 33.0  [0402L]  (hidden comment: ERJ-2RKF33R0X)
R60  ValueDisplayed: 33.0  [0402L]  (hidden comment: ERJ-2RKF33R0X)
R61  ValueDisplayed: 33.0  [0402L]  (hidden comment: ERJ-2RKF33R0X)
R62  ValueDisplayed: 0  [0603]  (hidden comment: RCS06030000Z0EA)
R63  ValueDisplayed: 0  [0603]  (hidden comment: RCS06030000Z0EA)
R64  ValueDisplayed: 0  [0603]  (hidden comment: RCS06030000Z0EA)
R65  ValueDisplayed: 0  [0603]  (hidden comment: RCS06030000Z0EA)
R66  ValueDisplayed: 0  [0603]  (hidden comment: RCS06030000Z0EA)
R67  ValueDisplayed: 0  [0603]  (hidden comment: RCS06030000Z0EA)
R68  ValueDisplayed: 0  [0603]  (hidden comment: RCS06030000Z0EA)
R69  ValueDisplayed: 0  [0603]  (hidden comment: RCS06030000Z0EA)
R70  ValueDisplayed: 0  [0603]  (hidden comment: RCS06030000Z0EA)
R71  ValueDisplayed: 0  [0603]  (hidden comment: RCS06030000Z0EA)
R72  ValueDisplayed: 0  [0603]  (hidden comment: RCS06030000Z0EA)
R73  ValueDisplayed: 0  [0603]  (hidden comment: RCS06030000Z0EA)
R74  ValueDisplayed: 0  [0603]  (hidden comment: RCS06030000Z0EA)
R75  ValueDisplayed: 0  [0603]  (hidden comment: RCS06030000Z0EA)
R76  ValueDisplayed: 0  [0603]  (hidden comment: RCS06030000Z0EA)
R77  ValueDisplayed: 0  [0603]  (hidden comment: RCS06030000Z0EA)
R78  ValueDisplayed: 0  [0603]  (hidden comment: RCS06030000Z0EA)
R79  ValueDisplayed: 33.0  [0402L]  (hidden comment: ERJ-2RKF33R0X)
R80  ValueDisplayed: 33.0  [0402L]  (hidden comment: ERJ-2RKF33R0X)
R81  ValueDisplayed: 680  [0603]  (hidden comment: RC0603JR-07680RL)
R82  ValueDisplayed: 680  [0603]  (hidden comment: RC0603JR-07680RL)
R84  ValueDisplayed: 0  [0603]  (hidden comment: RCS06030000Z0EA)
R86  ValueDisplayed: 0  [0603]  (hidden comment: RCS06030000Z0EA)
R88  ValueDisplayed: 0  [0603]  (hidden comment: RCS06030000Z0EA)
R233  ValueDisplayed: 680  [0603]  (hidden comment: RC0603JR-07680RL)
R334  ValueDisplayed: 0  [0603]  (hidden comment: RCS06030000Z0EA)
TP1  5011  [Keystone5011]  (value not drawn)
TP11  5011  [Keystone5011]  (value not drawn)
TP12  5011  [Keystone5011]  (value not drawn)
TP13  5011  [Keystone5011]  (value not drawn)
TP25  5011  [Keystone5011]  (value not drawn)
TP26  5011  [Keystone5011]  (value not drawn)

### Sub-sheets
U_TIDA-010957-DCAC-CAN = TIDA-010957-DCAC-CAN.SchDoc: CAN_TX (bidir), CAN_RX (bidir), CAN_EN (bidir)

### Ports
EN_AUX_ISO_DCAC (out), EN_BUFF_PWM_DCAC (out), FAN_CTRL (bidir), GRID_RELAYS (out), I_SENSE_PCC_L1 (in), I_SENSE_PCC_L2 (in), I_SENSE_PCC_L3 (in), I_SENSE_PCC_N (in), MONITOR_GaN_ISO_L1 (in), MONITOR_GaN_ISO_L2 (in), MONITOR_GaN_ISO_L3 (in), MONITOR_GaN_ISO_N (in), OC_L1 (in), OC_L2 (in), OC_L3 (in), OC_N (in), PWM_S1_GaN_L1 (out), PWM_S1_GaN_L2 (out), PWM_S1_GaN_L3 (out), PWM_S1_GaN_N (out), PWM_S2_GaN_L1 (out), PWM_S2_GaN_L2 (out), PWM_S2_GaN_L3 (out), PWM_S2_GaN_N (out), PWM_S3_GaN_L1 (out), PWM_S3_GaN_L2 (out), PWM_S3_GaN_L3 (out), PWM_S3_GaN_N (out), PWM_S4_GaN_L1 (out), PWM_S4_GaN_L2 (out), PWM_S4_GaN_L3 (out), PWM_S4_GaN_N (out), T_HEATSINK_DCAC (in), TEMP_S3_GaN_ISO_L1 (in), TEMP_S3_GaN_ISO_L2 (in), TEMP_S3_GaN_ISO_L3 (in), TEMP_S3_GaN_ISO_N (in), V_FC_L1 (in), V_FC_L2 (in), V_FC_L3 (in), V_FC_N (in), V_SENSE_DC (in), V_SENSE_PCC_L1 (in), V_SENSE_PCC_L2 (in), V_SENSE_PCC_L3 (in)

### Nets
1V65: C5.1 R38.1
5V: FB1.1
GND: C5.2 C15.1 C16.2 C159.1 C160.1 C161.1 C162.1 C173.1 C174.1 C175.1 C176.1 J12.7 J12.10 J12.16 J12.19 J12.22 J12.29 J12.35 J12.38 J12.46 J12.47 J12.65 J12.83 J12.97 J12.111 J13.1 J13.12 R23.2 R81.1 R82.1 R233.1 TP1.1 TP11.1 TP12.1 TP13.1 TP25.1 TP26.1
BUFF_EN: R65.1 ; port EN_BUFF_PWM_DCAC
CAN_EN: R88.1 ; sheet U_TIDA-010957-DCAC-CAN/CAN_EN
CAN_RX: R71.1 ; sheet U_TIDA-010957-DCAC-CAN/CAN_RX
CAN_TX: R84.1 ; sheet U_TIDA-010957-DCAC-CAN/CAN_TX
EN_AUX_ISO_DCAC: D19.2(ANODE) R67.1 ; port EN_AUX_ISO_DCAC
EN_BUFF_PWM_DCDC: R69.1
FAN_CTRL: R334.2 ; port FAN_CTRL
GPIO1: J12.86 R86.2
GPIO2: J12.88 R88.2
GPIO3: J12.90 R67.2
GPIO4: J12.92
GPIOA: J12.94 J13.7
GPIOB: J12.96 J13.6
GPIOC: J12.100 J13.5
GPIOD: J12.102 J13.4
GPIOE: J12.104 J13.3
GPIOF: J12.106 J13.2
GPIOG: J12.68
GRID_RELAYS: R63.1 ; port GRID_RELAYS
I_SENSE_1: R39.2
I_SENSE_2: R40.2
I_SENSE_PCC_L1: R21.2 ; port I_SENSE_PCC_L1
I_SENSE_PCC_L2: R32.1 ; port I_SENSE_PCC_L2
I_SENSE_PCC_L3: R20.2 ; port I_SENSE_PCC_L3
I_SENSE_PCC_N: R26.2 ; port I_SENSE_PCC_N
MONITOR_GaN_ISO_L1: C159.2 R68.2 ; port MONITOR_GaN_ISO_L1
MONITOR_GaN_ISO_L2: C160.2 R70.2 ; port MONITOR_GaN_ISO_L2
MONITOR_GaN_ISO_L3: C161.2 R72.2 ; port MONITOR_GaN_ISO_L3
MONITOR_GaN_ISO_N: C162.2 R73.2 ; port MONITOR_GaN_ISO_N
OC_L1: R62.2 ; port OC_L1
OC_L2: R64.2 ; port OC_L2
OC_L3: R66.2 ; port OC_L3
OC_N: R78.2 ; port OC_N
PWM_S1_GaN_A: J13.8 R29.1
PWM_S1_GaN_B: R59.1
PWM_S1_GaN_L1: R43.1 ; port PWM_S1_GaN_L1
PWM_S1_GaN_L2: R51.1 ; port PWM_S1_GaN_L2
PWM_S1_GaN_L3: R44.1 ; port PWM_S1_GaN_L3
PWM_S1_GaN_N: R52.1 ; port PWM_S1_GaN_N
PWM_S2_GaN_A: J13.9 R30.2
PWM_S2_GaN_B: R79.1
PWM_S2_GaN_L1: R47.1 ; port PWM_S2_GaN_L1
PWM_S2_GaN_L2: R55.1 ; port PWM_S2_GaN_L2
PWM_S2_GaN_L3: R48.1 ; port PWM_S2_GaN_L3
PWM_S2_GaN_N: R56.1 ; port PWM_S2_GaN_N
PWM_S3_GaN_A: J13.10 R61.1
PWM_S3_GaN_B: R80.1
PWM_S3_GaN_L1: R49.1 ; port PWM_S3_GaN_L1
PWM_S3_GaN_L2: R57.1 ; port PWM_S3_GaN_L2
PWM_S3_GaN_L3: R50.1 ; port PWM_S3_GaN_L3
PWM_S3_GaN_N: R58.1 ; port PWM_S3_GaN_N
PWM_S4_GaN_A: J13.11 R25.1
PWM_S4_GaN_B: R60.1
PWM_S4_GaN_L1: R45.1 ; port PWM_S4_GaN_L1
PWM_S4_GaN_L2: R53.1 ; port PWM_S4_GaN_L2
PWM_S4_GaN_L3: R46.1 ; port PWM_S4_GaN_L3
PWM_S4_GaN_N: R54.1 ; port PWM_S4_GaN_N
TEMP_S3_GaN_ISO_L1: C173.2 R74.2 ; port TEMP_S3_GaN_ISO_L1
TEMP_S3_GaN_ISO_L2: C174.2 R75.2 ; port TEMP_S3_GaN_ISO_L2
TEMP_S3_GaN_ISO_L3: C175.2 R76.2 ; port TEMP_S3_GaN_ISO_L3
TEMP_S3_GaN_ISO_N: C176.2 R77.2 ; port TEMP_S3_GaN_ISO_N
V_FC_L1: R31.2 ; port V_FC_L1
V_FC_L2: R22.2 ; port V_FC_L2
V_FC_L3: R27.2 ; port V_FC_L3
V_FC_N: R24.2 ; port V_FC_N
V_SENSE_1: R36.2
V_SENSE_2: R37.2
V_SENSE_3: R41.1
V_SENSE_4: R42.1 ; port T_HEATSINK_DCAC  [project net T_HEATSINK_DCAC]
V_SENSE_DC: R35.1 ; port V_SENSE_DC
V_SENSE_PCC_L1: R28.2 ; port V_SENSE_PCC_L1
V_SENSE_PCC_L2: R33.2 ; port V_SENSE_PCC_L2
V_SENSE_PCC_L3: R34.1 ; port V_SENSE_PCC_L3
NetC15_2: C15.2 C16.1 FB1.2 J12.48 J12.84 J12.98 J12.112
NetD1_1: D1.1(CATHODE) R81.2
NetD1_2: D1.2(ANODE) J12.107
NetD2_1: D2.1(CATHODE) R82.2
NetD2_2: D2.2(ANODE) J12.109
NetD19_1: D19.1(CATHODE) R233.2
NetJ12_9: J12.9 R20.1
NetJ12_11: J12.11 R21.1
NetJ12_12: J12.12 R22.1
NetJ12_13: J12.13 R23.1
NetJ12_14: J12.14 R24.1
NetJ12_15: J12.15 R25.2
NetJ12_17: J12.17 R26.1
NetJ12_18: J12.18 R27.1
NetJ12_20: J12.20 R28.1
NetJ12_21: J12.21 R29.2
NetJ12_24: J12.24 R30.1
NetJ12_25: J12.25 R31.1
NetJ12_26: J12.26 R32.2
NetJ12_27: J12.27 R33.1
NetJ12_28: J12.28 R34.2
NetJ12_30: J12.30 R35.2
NetJ12_31: J12.31 R36.1
NetJ12_33: J12.33 R37.1
NetJ12_36: J12.36 R38.2
NetJ12_37: J12.37 R39.1
NetJ12_39: J12.39 R40.1
NetJ12_40: J12.40 R41.2
NetJ12_42: J12.42 R42.2
NetJ12_49: J12.49 R43.2
NetJ12_50: J12.50 R44.2
NetJ12_51: J12.51 R45.2
NetJ12_52: J12.52 R46.2
NetJ12_53: J12.53 R47.2
NetJ12_54: J12.54 R48.2
NetJ12_55: J12.55 R49.2
NetJ12_56: J12.56 R50.2
NetJ12_57: J12.57 R51.2
NetJ12_58: J12.58 R52.2
NetJ12_59: J12.59 R53.2
NetJ12_60: J12.60 R54.2
NetJ12_61: J12.61 R55.2
NetJ12_62: J12.62 R56.2
NetJ12_63: J12.63 R57.2
NetJ12_64: J12.64 R58.2
NetJ12_67: J12.67 R59.2
NetJ12_69: J12.69 R60.2
NetJ12_70: J12.70 R61.2
NetJ12_71: J12.71 R62.1
NetJ12_72: J12.72 R63.2
NetJ12_73: J12.73 R64.1
NetJ12_74: J12.74 R65.2
NetJ12_75: J12.75 R66.1
NetJ12_77: J12.77 R68.1
NetJ12_78: J12.78 R69.2
NetJ12_79: J12.79 R70.1
NetJ12_80: J12.80 R71.2
NetJ12_81: J12.81 R72.1
NetJ12_82: J12.82 R84.2
NetJ12_87: J12.87 R73.1
NetJ12_89: J12.89 R74.1
NetJ12_91: J12.91 R75.1
NetJ12_93: J12.93 R76.1
NetJ12_95: J12.95 R77.1
NetJ12_99: J12.99 R78.1
NetJ12_101: J12.101 R334.1
NetJ12_108: J12.108 R79.2
NetJ12_110: J12.110 R80.2

Not connected (* = marked no-connect by the designer): J12 1* 2* 3* 4* 5* 6* 8* 23* 32* 34* 41* 43* 44* 45* 66* 76 85* 103* 105* 113* 114* 115* 116* 117* 118* 119* 120*; R86 1*

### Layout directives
net class LV_NET: 1V65, 5V, CAN_EN, CAN_RX, CAN_TX, EN_BUFF_PWM_DCDC, GND, GPIO1, GPIO2, GPIO3, GPIO4, GPIOA, GPIOB, GPIOC, GPIOD, GPIOE, GPIOF, GPIOG, I_SENSE_1, I_SENSE_2, PWM_S1_GaN_A, PWM_S1_GaN_B, PWM_S2_GaN_A, PWM_S2_GaN_B, PWM_S3_GaN_A, PWM_S3_GaN_B, PWM_S4_GaN_A, PWM_S4_GaN_B, V_SENSE_1, V_SENSE_2, V_SENSE_3, V_SENSE_4

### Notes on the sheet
- ADCA: 1,6,7,10,
- CMPSS1-A1
- CMPSS3-C15
- X
- B26
- ADCB: 5,8,26,27,
- ADCC: 1,6,15,
- ADCD: 5,6,13,19
- PMW11A
- PMW11B
- D5
- C1
- A10
- B27
- ADCE: 8,9,18,20,
- A6
- B5
- D13
- C6
- A7
- PMW12A
- CMPSS2-B8
- D6
- E9
- E20
- E8
- D19
- E18
- PMW1A
- PMW1B
- (near R40) No rounting for no port signals
- PMW3A
- PMW3B
- PMW2A
- PMW2B
- PMW5A
- PMW5B
- PMW4A
- PMW4B
- PMW7A
- PMW7B
- PMW6A
- PMW6B
- PMW9A
- PMW9B
- PMW12B
- PMW8A
- PMW8B
- GPIO22
- GPIO59
- (near R88) GPIO44
- PMW10A
- PMW10B
- (near J13) Check if one of the pins as DAC
- Monitor the local 1.65 V

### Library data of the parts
C5 C159-C162 C173-C176 = CMP-0095085-1: Cap Ceramic 330pF 50V C0G 5% Pad SMD 0603 +125°C Automotive T/R; Manufacturer: TDK; AEC Qualified: Yes; TempCo: 30ppm/°C; Tolerance_%: 0.05%; AEC Grade: Grade 1; SizeZ_mm: 1.1mm
C15 = CMP-0086152-1: CAP, CERM, 1 µF, 25 V,+/- 10%, X5R, 0603; Manufacturer: Taiyo Yuden; SizeAreaWB_mm2: 4.68; SizeZ_mm: 1; U/M: EA; Green_REACh: Passed; Value: 1uF; AEC Qualified: N; TaMax_C: 85°C; Green_Lifecycle: Active; AEC Category: Q200; SizeArea_mm2: 1.28; TaMin_C: -55°C; SizeY_mm: 0.8; SizeX_mm: 1.6
C16 = CMP-0006752-5: CAP, CERM, 0.1 uF, 25 V, +/- 5%, X7R, 0603; Manufacturer: AVX; TaMin_C: -55°C; ESR_ohm: 0.05; Polarized: N; SizeAreaWB_mm2: 4.68; Value1: 0.05 ohm; U/M: EA; Value: 0.1uF; TaMax_C: 125°C; SizeZ_mm: 1; SizeX_mm: 1.6; SizeY_mm: 0.8; SizeArea_mm2: 1.28; AEC Category: Q200
D1 D2 D19 = CMP-0093310-1: Standard LEDs - SMD Green TOPLED E 1608; Manufacturer: Osram Opto; AEC Grade: Grade 2; LambdaP: 572nm; SizeZ_mm: 0.7mm; LuminousFlux_PhiV: 0.016-0.0295lm; Luminous Intensity: 4.5-9.7mcd; LambdaD: 570nm; Tjmax_C: 125°C; Angle: 120°; Led Orientation: Top View; Forward Current: 2mA; Vf_V: 1.8V; AEC Qualified: Yes; Vr_V: 12V
FB1 = CMP-0037505-1: 600 Ohms @ 100 MHz 1 Power, Signal Line Ferrite Bead 0603 (1608 Metric) 1A 200mOhm; Manufacturer: Bourns; DCR_ohm: 0.2; SizeZ_mm: 1mm; AEC Qualified: No; Impedance At Frequency: 600Ω @ 100MHz; Test Frequency: 100MHz; Tolerance_%: 25%
J12 = CMP-0003814-2: C2000 controlCARD-120HSEC connector, SMT; Manufacturer: Samtec; Note: The pin numbering does not match Samtec datasheet
J13 = CMP-0075424-1: Header, 100mil, 12x1, Gold, TH; Manufacturer: Samtec; Pitch_mm: 2.54; Cert_VDE: N; Gender: Male; Cert_CSA: Y; Current_A: 6.3A; Voltage_V: 550V; CT: False; Row_Count: 1; CNHeader: True
R20-R24 R26-R28 R31-R42 R62-R78 R84 R86 R88 R334 = CMP-0081973-1: RES, 0, 0%, 0.25 W, AEC-Q200 Grade 0, 0603; Manufacturer: Vishay-Dale; SizeAreaWB_mm2: 4.68; SizeArea_mm2: 1.28; AEC Qualified: Y; AEC Category: Q200; Value: 0; SizeZ_mm: 1; SizeY_mm: 0.8; Power_W: 250mW; Value2: 0.25W; SizeX_mm: 1.6
R25 R29 R30 R43-R61 R79 R80 = CMP-0026696-1: RES, 33.0, 1%, 0.1 W, 0402; Manufacturer: Panasonic; Power_W: 100mW; TempCo: 100 ppm/C; Value_Code: 33R0; U/M: EA; Value: 33.0; Res_ohm: 33; SizeX_mm: 1; SizeY_mm: 0.5; SizeZ_mm: 0.6; Value2: 0.1W; VDC_V: 50V; AEC Category: Q200
R81 R82 R233 = CMP-0025936-5: RES, 680, 5%, 0.1 W, 0603; Manufacturer: Yageo; Power_W: 100mW; TempCo: 100 ppm/C; Value_Code: 680R; Value: 680; EIA_Code: E24; SizeX_mm: 1.6; SizeY_mm: 0.8; SizeZ_mm: 1; Value2: 0.1W; SizeArea_mm2: 1.28; AEC Qualified: N; VDC_V: 75V; AEC Category: Q200; SizeAreaWB_mm2: 4.68
TP1 TP11-TP13 TP25 TP26 = CMP-0055148-2: as TP8 on sheet TIDA-010957-DCAC-Overview

## Sheet TIDA-010957-DCAC-CAN.SchDoc
size A3; Date: Not shown in title block; ApprovedBy: Not shown in title block; CheckedBy: Not shown in title block; Author: Not shown in title block; CompanyName: Not shown in title block; Engineer: Not shown in title block; Organization: Not shown in title block; Address1: Not shown in title block; Address2: Not shown in title block; Address3: Not shown in title block; Address4: Not shown in title block; DocumentNumber: 1; Revision: Use project parameter SCH_Rev; SheetNumber: 4; SheetTotal: 12; PageSetup: Record=PageOptions¦CenterHorizontal=True¦CenterVertical=True¦PrintScale=0.69¦XCorrection=1.00¦YCorrection=1.00¦PrintKind=0¦BorderSize=5000000¦LeftOffset=0¦BottomOffset=0¦Orientation=2¦PaperLength=1000¦PaperWidth=1000¦Scale=100¦PaperSource=15¦PrintQuality=600¦MediaType=1¦DitherType=10¦PaperKind=Letter¦PrintScaleMode=1
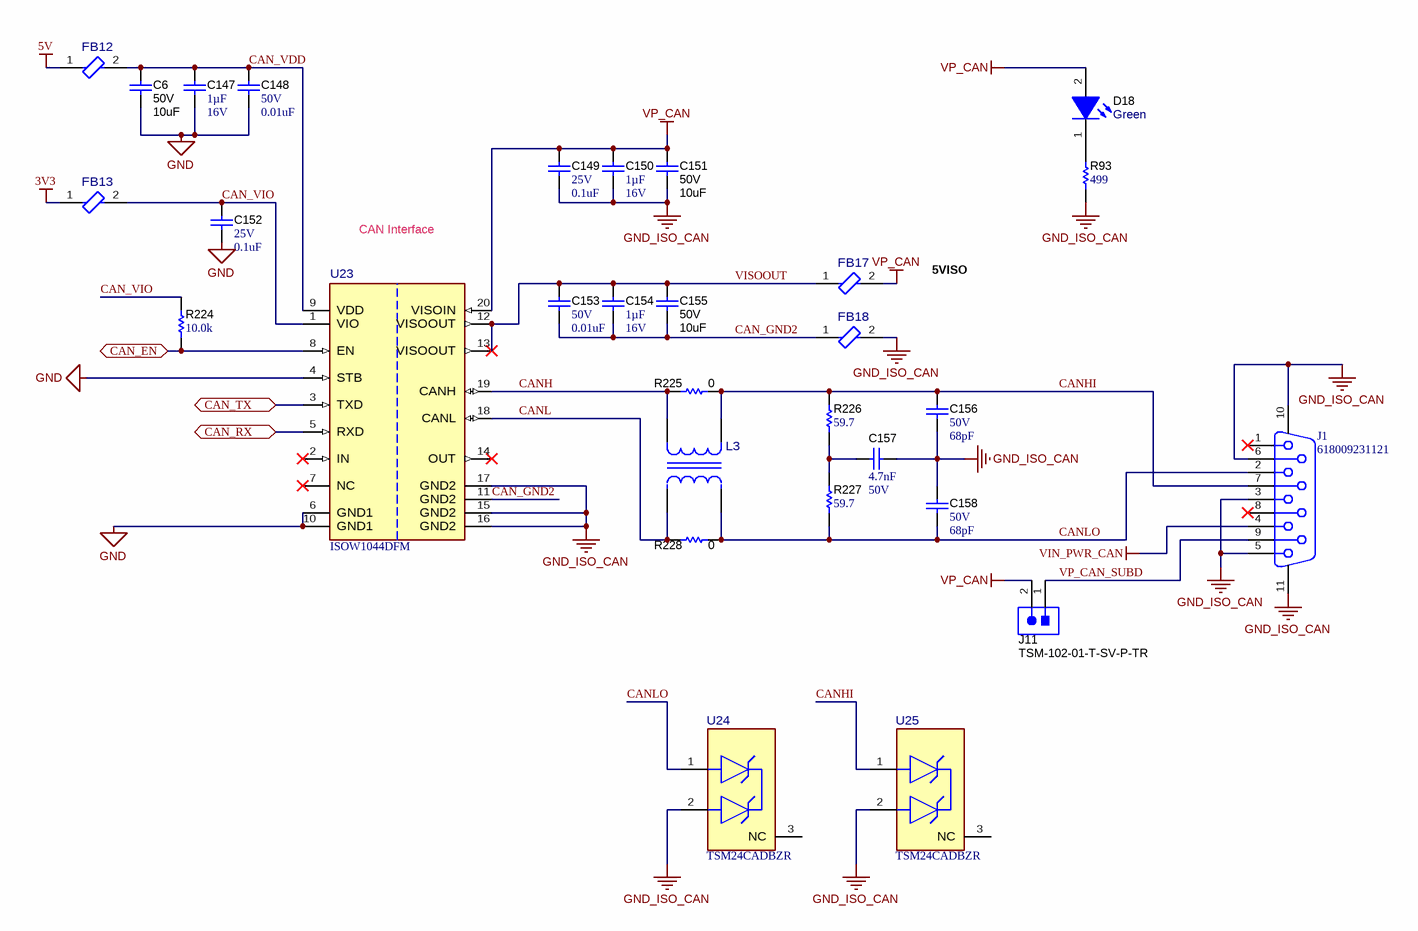
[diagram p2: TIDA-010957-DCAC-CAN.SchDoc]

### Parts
C6  VDC_V: 50V  ValueDisplayed: 10uF  [1206_180L]  (hidden comment: CL31B106KBHNNNE)
C147  Cap_F: 1µF  VDC_V: 16V  [0603]  (hidden comment: GCM188R71C105KA64J)
C148  VDC_V: 50V  ValueDisplayed: 0.01uF  [0402]  (hidden comment: GRM155R71H103KA88D)
C149  VDC_V: 25V  ValueDisplayed: 0.1uF  [0402]  (hidden comment: GRM155R71E104KE14D)
C150  Cap_F: 1µF  VDC_V: 16V  [0603]  (hidden comment: GCM188R71C105KA64J)
C151  VDC_V: 50V  ValueDisplayed: 10uF  [1206_180L]  (hidden comment: CL31B106KBHNNNE)
C152  VDC_V: 25V  ValueDisplayed: 0.1uF  [0402]  (hidden comment: GRM155R71E104KE14D)
C153  VDC_V: 50V  ValueDisplayed: 0.01uF  [0402]  (hidden comment: GRM155R71H103KA88D)
C154  Cap_F: 1µF  VDC_V: 16V  [0603]  (hidden comment: GCM188R71C105KA64J)
C155  VDC_V: 50V  ValueDisplayed: 10uF  [1206_180L]  (hidden comment: CL31B106KBHNNNE)
C156  VDC_V: 50V  ValueDisplayed: 68pF  [0402]  (hidden comment: C1005C0G1H680J050BA)
C157  Cap_F: 4.7nF  VDC_V: 50V  [0603]  (hidden comment: C0603X472K5RACTU)
C158  VDC_V: 50V  ValueDisplayed: 68pF  [0402]  (hidden comment: C1005C0G1H680J050BA)
D18  value Green  [WL-SMCW_GREEN]  (hidden comment: 150060VS75000)
FB12  BLM15EX331SN1D  [FP-BLM15EX331SN1D_0402-MFG]  (value not drawn)
FB13  BLM15EX331SN1D  [FP-BLM15EX331SN1D_0402-MFG]  (value not drawn)
FB17  BLM15EX331SN1D  [FP-BLM15EX331SN1D_0402-MFG]  (value not drawn)
FB18  BLM15EX331SN1D  [FP-BLM15EX331SN1D_0402-MFG]  (value not drawn)
J1  618009231121  [Wurth_618009231121]
J11  TSM-102-01-T-SV-P-TR  [Samtec_TSM-102-01-T-SV-P-TR]
L3  ACT45B-101-2P-TL003  [FP-ACT45B-101-2P-TL003_SMT_4MM5_3MM2-MFG]  (value not drawn)
R93  ValueDisplayed: 499  [0603]  (hidden comment: CRCW0603499RFKEAC)
R224  ValueDisplayed: 10.0k  [0402]  (hidden comment: CRCW040210K0FKED)
R225  ValueDisplayed: 0  [0603]  (hidden comment: RCS06030000Z0EA)
R226  ValueDisplayed: 59.7  [0603]  (hidden comment: RT0603DRE0759R7L)
R227  ValueDisplayed: 59.7  [0603]  (hidden comment: RT0603DRE0759R7L)
R228  ValueDisplayed: 0  [0603]  (hidden comment: RCS06030000Z0EA)
U23  ISOW1044DFM  [DFM0020A-MFG]
U24  TSM24CADBZR  [DBZ0003A-MFG]
U25  TSM24CADBZR  [DBZ0003A-MFG]

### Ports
CAN_EN (bidir), CAN_RX (bidir), CAN_TX (bidir)

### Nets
3V3: FB13.1
5V: FB12.1
GND: C6.2 C147.2 C148.2 C152.2 U23.4(STB) U23.6(GND1) U23.10(GND1)
GND_ISO_CAN: C149.2 C150.2 C151.2 C156.2 C157.1 C158.1 FB18.2 J1.3 J1.5 J1.6 J1.10 J1.11 R93.1 U23.15(GND2) U23.16(GND2) U23.17(GND2) U24.2(2_IO) U25.2(2_IO)
VIN_PWR_CAN: J1.4
VP_CAN: C149.1 C150.1 C151.1 D18.2(A) FB17.2 J11.2 U23.20(VISOIN)
CAN_EN: R224.1 U23.8(EN) ; port CAN_EN
CAN_GND2: C153.2 C154.2 C155.2 FB18.1 U23.11(GND2)
CAN_RX: U23.5(RXD) ; port CAN_RX
CAN_TX: U23.3(TXD) ; port CAN_TX
CAN_VDD: C6.1 C147.1 C148.1 FB12.2 U23.9(VDD)
CAN_VIO: C152.1 FB13.2 R224.2 U23.1(VIO)
CANH: L3.1 R225.2 U23.19(CANH)
CANHI: C156.1 J1.7 L3.4 R225.1 R226.2 U25.1(1_IO)
CANL: L3.2 R228.2 U23.18(CANL)
CANLO: C158.2 J1.2 L3.3 R227.1 R228.1 U24.1(1_IO)
VISOOUT: C153.1 C154.1 C155.1 FB17.1 U23.12(VISOOUT) U23.13(VISOOUT)
VP_CAN_SUBD: J1.9 J11.1
NetC157_2: C157.2 R226.1 R227.2
NetD18_1: D18.1(K) R93.2

Not connected (* = marked no-connect by the designer): J1 1* 8*; U23 2(IN)* 7(NC)* 14(OUT)*; U24 3(NC); U25 3(NC)

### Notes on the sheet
- CAN Interface
- 5VISO

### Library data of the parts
C6 C151 C155 = CMP-0008802-2: CAP, CERM, 10 uF, 50 V, +/- 10%, X7R, 1206; Manufacturer: Samsung; TaMin_C: -55°C; Polarized: N; SizeAreaWB_mm2: 10.92; Value1: Unknown; U/M: EA; Value: 10uF; TaMax_C: 125°C; SizeZ_mm: 1.8; SizeX_mm: 3.2; SizeY_mm: 1.6; Cap_Case: 1206; SizeArea_mm2: 5.12; Cap_F: 10µF; AEC Category: Q200
C147 C150 C154 = CMP-0079154-1: CAP, CERM, 1 µF, 16 V,+/- 10%, X7R, AEC-Q200 Grade 1, 0603; Manufacturer: MuRata; SizeAreaWB_mm2: 4.68; SizeArea_mm2: 1.28; AEC Qualified: Y; AEC Category: Q200; Value: 1uF; TaMax_C: 125°C; SizeZ_mm: 1; Polarized: N; TaMin_C: -55°C; SizeY_mm: 0.8; U/M: EA; SizeX_mm: 1.6
C148 C153 = CMP-0006674-2: CAP, CERM, 0.01 uF, 50 V, +/- 10%, X7R, 0402; Manufacturer: MuRata; TaMin_C: -55°C; Polarized: N; SizeAreaWB_mm2: 3; Value1: Unknown; U/M: EA; Value: 0.01uF; TaMax_C: 125°C; SizeZ_mm: 0.6; SizeX_mm: 1; SizeY_mm: 0.5; Cap_F: 10nF; AEC Category: Q200
C149 C152 = CMP-0006659-2: CAP, CERM, 0.1 uF, 25 V, +/- 10%, X7R, 0402; Manufacturer: MuRata; TaMin_C: -55°C; Polarized: N; SizeAreaWB_mm2: 3; Value1: Unknown; U/M: EA; Value: 0.1uF; TaMax_C: 125°C; SizeZ_mm: 0.6; SizeX_mm: 1; SizeY_mm: 0.5; Cap_F: 100nF; AEC Category: Q200
C156 C158 = CMP-0006251-2: CAP, CERM, 68 pF, 50 V, +/- 5%, C0G/NP0, 0402; Manufacturer: TDK; TaMin_C: -55°C; Polarized: N; SizeAreaWB_mm2: 3; Value1: Unknown; U/M: EA; Value: 68pF; TaMax_C: 125°C; SizeZ_mm: 0.6; SizeX_mm: 1; SizeY_mm: 0.5; AEC Category: Q200
C157 = CMP-0006987-4: CAP, CERM, 4700 pF, 50 V, +/- 10%, X7R, 0603; Manufacturer: Kemet; TaMin_C: -55°C; Polarized: N; SizeAreaWB_mm2: 4.68; Value1: Unknown; U/M: EA; Value: 4700pF; TaMax_C: 125°C; SizeZ_mm: 1; SizeX_mm: 1.6; SizeY_mm: 0.8; SizeArea_mm2: 1.28; AEC Category: Q200
D18 = CMP-0002894-2: LED, Green, SMD; Manufacturer: Wurth Elektronik; Type: AlInGaP; Value2: 2V; Io_A: 20mA; Value1: W
FB12 FB13 FB17 FB18 = CMP-0041881-1: Chip Ferrite Bead, 0402, 330Ω @ 100MHz, 0.205Ω, 25%, 1.1A; Manufacturer: Murata; DCR_ohm: 0.205; SizeZ_mm: 0.55mm; AEC Qualified: No; Ciiva Ids: 2806665; Import Ts: 1521856324
J1 = CMP-0054820-2: Receptacle, D-Sub, 9 Position, R/A, TH; Manufacturer: Wurth Elektronik; Pitch_mm: 2.77; Gender: Female; Cert_UL: Y; Voltage_V: 125V; ContactFinish: Gold; Row_Count: 2; Current_A: 3A; CNHeader: FALSE; CT: TRUE
J11 = CMP-0075491-1: Header, 100mil, 2x1, Tin, SMD; Manufacturer: Samtec; Pitch_mm: 2.54; Gender: Male; Cert_CSA: Y; Current_A: 5.4A; Voltage_V: 475V; CT: False; Shrouded: N; Row_Count: 1; CNHeader: True
L3 = CMP-0084086-1: 100µH @ 100kHz 2 Line Common Mode Choke Surface Mount 5.8 kOhms @ 10MHz 150mA DCR 2Ohm; Manufacturer: TDK; AEC Grade: Grade 0; Tolerance_%: +50/-30%; AEC Qualified: Yes; Ind_H: 100uH; SizeZ_mm: 3mm; DCR_ohm: 2Ω; Impedance At Frequency: 5800Ω @ 10MHz; Imax_A: 0.15A
R93 = CMP-0082532-1: RES, 499, 1%, 0.1 W, 0603; Manufacturer: Vishay-Dale; Power_W: 100mW; TempCo: 100 ppm/C; SizeAreaWB_mm2: 4.68; Value_Code: 499R; Value: 499; EIA_Code: E96; SizeX_mm: 1.6; SizeY_mm: 0.8; SizeZ_mm: 1; Value2: 0.1W; SizeArea_mm2: 1.28; AEC Qualified: N; VDC_V: 75V; AEC Category: Q200
R224 = CMP-0025958-3: RES, 10.0 k, 1%, 0.063 W, AEC-Q200 Grade 0, 0402; Manufacturer: Vishay-Dale; Power_W: 63mW; TempCo: 100 ppm/C; Value_Code: 10k0; Value: 10.0k; EIA_Code: E96; Res_ohm: 10k; SizeX_mm: 1; SizeY_mm: 0.5; SizeZ_mm: 0.6; Value2: 0.063W; AEC Qualified: Y; VDC_V: 50V; AEC Category: Q200; AEC Grade: 0
R225 R228 = CMP-0081973-1: as R20 on sheet TIDA-010957-DCAC-CONTROLLER
R226 R227 = CMP-0025431-3: RES, 59.7, 0.5%, 0.1 W, 0603; Manufacturer: Yageo America; Power_W: 100mW; TempCo: 50 ppm/C; Value_Code: 59R7; U/M: EA; Value: 59.7; EIA_Code: E192; SizeX_mm: 1.6; SizeY_mm: 0.8; SizeZ_mm: 1; Value2: 0.1W; SizeArea_mm2: 1.28; VDC_V: 75V; AEC Category: Q200
U23 = CMP-0092023-2: Reinforced 5-kVRMS Isolated CAN Transceiver with Integrated lowemissions DC-DC Converter; Manufacturer: Texas Instruments; TJmax_C: +150°C; Max Supply Voltage: 5.5V; AEC Qualified: No; Standoff Height: 0.1mm; Nominal Supply Current: 0.3-124mA; CompType: IC; AEC Category: Q200; TaMax_C: +105°C; SizeZ_mm: 3.55mm; Min Supply Voltage: 1.71V; TaMin_C: -40°C
U24 U25 = CMP-0120116-1: ±24 V Low Capacitance Surge Diode for Industrial Networks in SOT-23 Package; Manufacturer: Texas Instruments; SizeZ_mm: 1.12mm; AEC Qualified: No; Breakdown Voltage: 25.5V; Cap_F: 14pF; Clamping Voltage: 35V; Direction: Bidirectional; Ipp: 30A; Number Of Channels: 1; Ppk: 1200W; Standoff Height: 0.01mm; TaMax_C: +125°C; TaMin_C: -40°C; VRWM: 24V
